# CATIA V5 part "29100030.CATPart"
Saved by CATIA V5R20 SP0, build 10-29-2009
Part number: 29100030
Definition: NONE
Nomenclature: 29100030
Source: Unknown
Description: 29100030
Bounding box of the stored display mesh (mm): x -15 to 44.548, y -64 to 98.548, z -54 to 54
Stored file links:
  C:\Users\Utente\Desktop\IO LAVORO\3D X SITO CF\X SITO\PLASTICA\RF1\29100030.CATPart
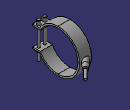
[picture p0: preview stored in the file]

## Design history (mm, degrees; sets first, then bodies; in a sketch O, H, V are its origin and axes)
Body1 "29100030" (main body)
  Solid1: solid without history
